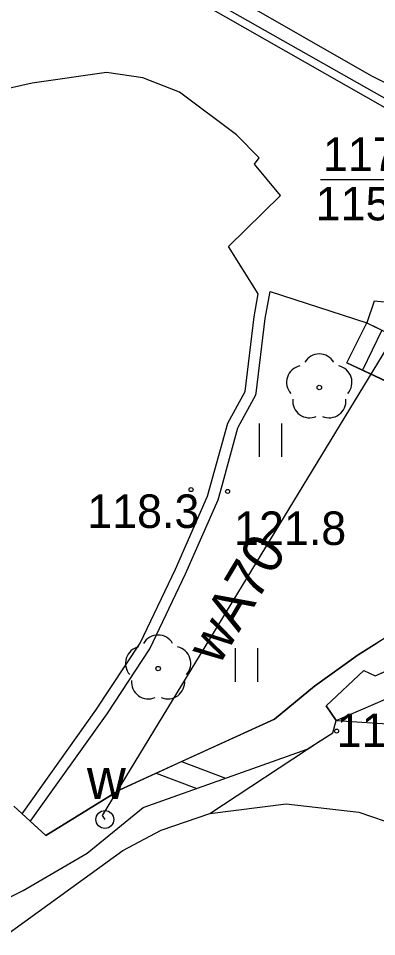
# Model space of a CAD drawing. Extents: x 6434771 to 6436222, y 5663454 to 5664782.
# Drawn here: x 6435156.83 to 6435164.85, y 5663876.46 to 5663897 of the extents above; entities that cross this region are included whole.
import ezdxf

# ---------------------------------------------------------------- set-up
doc = ezdxf.new("R2010")
doc.units = 0
for name, color, linetype in [('Warstwa 11', 7, 'Continuous'), ('Warstwa 12', 7, 'Continuous'), ('Warstwa 13', 7, 'Continuous'), ('Warstwa 14', 7, 'Continuous'), ('Warstwa 25', 7, 'Continuous'), ('Warstwa 34', 7, 'Continuous'), ('Warstwa 36', 7, 'Continuous'), ('Warstwa 4', 7, 'Continuous'), ('Warstwa 5', 7, 'Continuous'), ('Warstwa 51', 7, 'Continuous'), ('Warstwa 6', 7, 'Continuous'), ('Warstwa 9', 7, 'Continuous')]:
    doc.layers.add(name, color=color, linetype=linetype)

msp = doc.modelspace()

# ---------------------------------------------------------------- linework, layer by layer
at = {"layer": 'Warstwa 11'}
for centre in [(6435163.565, 5663888.741), (6435159.958, 5663882.454)]:
    msp.add_circle(centre, 0.05, dxfattribs=at)
for centre, start, end in [((6435163.565, 5663889.116), 30.1471, 149.8529), ((6435163.208, 5663888.857), 102.1471, 221.8529), ((6435163.922, 5663888.857), 318.1471, 77.8529), ((6435163.345, 5663888.438), 174.1471, 293.8529), ((6435163.785, 5663888.438), 246.1471, 5.8529), ((6435159.958, 5663882.829), 30.1471, 149.8529), ((6435159.601, 5663882.57), 102.1471, 221.8529), ((6435160.315, 5663882.57), 318.1471, 77.8529), ((6435159.738, 5663882.151), 174.1471, 293.8529), ((6435160.178, 5663882.151), 246.1471, 5.8529)]:
    msp.add_arc(centre, 0.375, start, end, dxfattribs=at)
at = {"layer": 'Warstwa 12'}
for points in [[(6435063.696, 5663930.091), (6435072.471, 5663935.396), (6435084.159, 5663937.604), (6435099.338, 5663932.48), (6435124.367, 5663918.137), (6435165.517, 5663894.728), (6435170.23, 5663892.401), (6435196.432, 5663878.313), (6435197.764, 5663876.037), (6435200.507, 5663874.574)], [(6435243.45, 5663833.342), (6435243.347, 5663833.392), (6435243.041, 5663835.668), (6435233.883, 5663842.599), (6435229.544, 5663847.621), (6435230.488, 5663855.43), (6435227.071, 5663861.482), (6435200.606, 5663877.013), (6435196.659, 5663878.93), (6435171.937, 5663892.14), (6435164.739, 5663895.707), (6435120.054, 5663921.259), (6435106.974, 5663928.778), (6435090.917, 5663933.312), (6435076.731, 5663934.584), (6435064.319, 5663933.634), (6435061.286, 5663934.067)], [(6435184.91, 5663855.561), (6435186.088, 5663855.747), (6435193.004, 5663868.644), (6435194.726, 5663873.753), (6435194.748, 5663876.343), (6435193.834, 5663878.494), (6435189.316, 5663882.019), (6435172.175, 5663891.167), (6435167.238, 5663893.957), (6435152.766, 5663902.142), (6435132.535, 5663913.808), (6435121.373, 5663919.463), (6435119.301, 5663920.188), (6435117.575, 5663919.659), (6435117.521, 5663919.329)], [(6435167.474, 5663893.574), (6435158.708, 5663879.169)], [(6435158.708, 5663879.169), (6435158.767, 5663879.078)]]:
    msp.add_lwpolyline(points, dxfattribs=at)
at = {"layer": 'Warstwa 13'}
for centre in [(6435160.695, 5663886.457), (6435161.513, 5663886.416)]:
    msp.add_circle(centre, 0.045, dxfattribs=at)
at = {"layer": 'Warstwa 14'}
msp.add_lwpolyline([(6435163.591, 5663893.392), (6435165.963, 5663893.392), (6435167.443, 5663894.649)], dxfattribs=at)
at = {"layer": 'Warstwa 25'}
msp.add_circle((6435163.953, 5663881.055), 0.045, dxfattribs=at)
at = {"layer": 'Warstwa 34'}
msp.add_lwpolyline([(6435153.176, 5663874.056), (6435159.169, 5663878.384), (6435160.025, 5663878.843), (6435161.119, 5663879.21), (6435162.822, 5663879.429), (6435164.45, 5663879.24), (6435166.193, 5663878.649), (6435167.574, 5663877.902), (6435169.218, 5663876.592), (6435170.611, 5663875.115), (6435171.692, 5663873.592), (6435172.76, 5663871.739), (6435173.45, 5663870.11), (6435174.095, 5663868.012), (6435174.509, 5663865.887), (6435174.586, 5663863.966), (6435174.454, 5663862.118), (6435174.208, 5663860.831), (6435173.802, 5663859.496), (6435173.168, 5663858.343), (6435170.883, 5663860.431)], dxfattribs=at)
at = {"layer": 'Warstwa 36'}
msp.add_line((6435164.962, 5663890.024), (6435164.531, 5663889.126), dxfattribs=at)
for points in [[(6435164.632, 5663890.185), (6435165.438, 5663889.791), (6435165.798, 5663890.573), (6435164.791, 5663890.67)], [(6435164.632, 5663890.185), (6435165.951, 5663889.54), (6435165.574, 5663888.64), (6435164.182, 5663889.289)]]:
    msp.add_lwpolyline(points, close=True, dxfattribs=at)
at = {"layer": 'Warstwa 4'}
msp.add_circle((6435158.767, 5663879.078), 0.2, dxfattribs=at)
at = {"layer": 'Warstwa 5'}
for p, q in [((6435162.351, 5663890.281), (6435162.464, 5663890.889)), ((6435162.464, 5663890.889), (6435164.632, 5663890.185)), ((6435162.15, 5663888.613), (6435162.351, 5663890.281)), ((6435164.182, 5663889.289), (6435164.632, 5663890.185)), ((6435164.182, 5663889.289), (6435165.574, 5663888.64)), ((6435161.748, 5663887.851), (6435162.145, 5663888.573)), ((6435162.145, 5663888.573), (6435162.15, 5663888.613)), ((6435161.39, 5663886.55), (6435161.744, 5663887.837)), ((6435161.744, 5663887.837), (6435161.748, 5663887.851)), ((6435162.227, 5663887.189), (6435162.227, 5663887.939)), ((6435162.727, 5663887.189), (6435162.727, 5663887.939)), ((6435161.301, 5663886.227), (6435161.39, 5663886.55)), ((6435160.572, 5663884.576), (6435161.301, 5663886.227)), ((6435159.773, 5663882.896), (6435160.572, 5663884.576)), ((6435163.945, 5663881.296), (6435169.464, 5663883.689)), ((6435161.688, 5663882.159), (6435161.688, 5663882.909)), ((6435162.188, 5663882.159), (6435162.188, 5663882.909)), ((6435164.432, 5663882.76), (6435164.884, 5663883.042)), ((6435158.815, 5663881.443), (6435159.773, 5663882.896)), ((6435163.454, 5663882.062), (6435164.432, 5663882.76)), ((6435162.565, 5663881.323), (6435163.454, 5663882.062)), ((6435157.12, 5663879.06), (6435158.815, 5663881.443)), ((6435160.481, 5663880.372), (6435162.565, 5663881.323)), ((6435163.871, 5663881.017), (6435163.945, 5663881.296)), ((6435163.945, 5663881.296), (6435166.972, 5663881.089)), ((6435163.945, 5663881.296), (6435166.972, 5663881.089)), ((6435163.584, 5663880.836), (6435163.871, 5663881.017)), ((6435161.119, 5663879.21), (6435163.584, 5663880.836)), ((6435159.913, 5663880.113), (6435160.481, 5663880.372)), ((6435159.105, 5663879.744), (6435159.913, 5663880.113)), ((6435157.443, 5663878.724), (6435159.105, 5663879.744)), ((6435161.119, 5663879.21), (6435162.822, 5663879.429)), ((6435162.822, 5663879.429), (6435164.45, 5663879.24)), ((6435164.45, 5663879.24), (6435166.193, 5663878.649)), ((6435157.096, 5663879.04), (6435157.12, 5663879.06)), ((6435157.096, 5663879.04), (6435157.443, 5663878.724))]:
    msp.add_line(p, q, dxfattribs=at)
at = {"layer": 'Warstwa 51'}
for p, q in [((6435160.481, 5663880.372), (6435161.468, 5663880.004)), ((6435159.913, 5663880.113), (6435160.821, 5663879.775))]:
    msp.add_line(p, q, dxfattribs=at)
for points in [[(6435156.916, 5663879.205), (6435158.567, 5663881.521), (6435159.555, 5663883.019), (6435160.345, 5663884.68), (6435161.065, 5663886.311), (6435161.515, 5663887.946), (6435161.903, 5663888.651), (6435162.104, 5663890.319), (6435162.2, 5663890.838), (6435161.533, 5663891.896), (6435162.697, 5663893.032), (6435162.115, 5663893.739), (6435162.217, 5663893.878), (6435161.713, 5663894.394), (6435160.434, 5663895.349), (6435159.618, 5663895.669), (6435158.8, 5663895.789), (6435157.137, 5663895.549), (6435155.913, 5663895.274)], [(6435185.06, 5663865.07), (6435185.513, 5663867.724), (6435185.479, 5663869.895), (6435185.078, 5663872.34), (6435184.856, 5663872.993), (6435183.229, 5663876.523), (6435182.357, 5663877.993), (6435180.725, 5663880.323), (6435179.379, 5663881.559), (6435178.16, 5663882.414), (6435173.755, 5663884.588), (6435171.13, 5663885.009), (6435168.326, 5663884.693), (6435166.95, 5663884.21), (6435165.863, 5663883.653), (6435164.432, 5663882.76), (6435163.454, 5663882.062), (6435162.565, 5663881.323), (6435159.105, 5663879.744), (6435157.443, 5663878.724), (6435156.731, 5663879.373)], [(6435154.584, 5663876.329), (6435156.938, 5663877.49), (6435158.368, 5663878.323), (6435159.621, 5663879.348), (6435163.297, 5663880.654), (6435163.871, 5663881.017), (6435163.945, 5663881.296), (6435163.719, 5663881.619), (6435164.558, 5663882.409), (6435164.817, 5663882.295), (6435168.507, 5663883.911)]]:
    msp.add_lwpolyline(points, dxfattribs=at)
at = {"layer": 'Warstwa 9'}
for p, q in [((6435163.945, 5663881.296), (6435169.464, 5663883.689)), ((6435164.817, 5663882.295), (6435165.749, 5663882.703)), ((6435163.719, 5663881.619), (6435164.558, 5663882.409)), ((6435164.558, 5663882.409), (6435164.817, 5663882.295)), ((6435163.719, 5663881.619), (6435163.945, 5663881.296))]:
    msp.add_line(p, q, dxfattribs=at)

# ---------------------------------------------------------------- texts
at = {"layer": 'Warstwa 13'}
for s, p in [('118.3', (6435158.372, 5663885.599)), ('121.8', (6435161.657, 5663885.218))]:
    msp.add_text(s, height=0.75, dxfattribs=at).set_placement(p)
msp.add_text('wA70', height=0.9, rotation=59.2839, dxfattribs=at).set_placement((6435161.317, 5663882.499))
at = {"layer": 'Warstwa 14'}
msp.add_text('115.90', height=0.75, dxfattribs=at).set_placement((6435163.485, 5663892.478))
at = {"layer": 'Warstwa 25'}
msp.add_text('118.02', height=0.75, dxfattribs=at).set_placement((6435163.955, 5663880.697))
at = {"layer": 'Warstwa 5'}
msp.add_text('w', height=0.9, dxfattribs=at).set_placement((6435158.366, 5663879.537))
at = {"layer": 'Warstwa 6'}
msp.add_text('117.60', height=0.75, dxfattribs=at).set_placement((6435163.645, 5663893.584))

doc.saveas('drawing.dxf')
